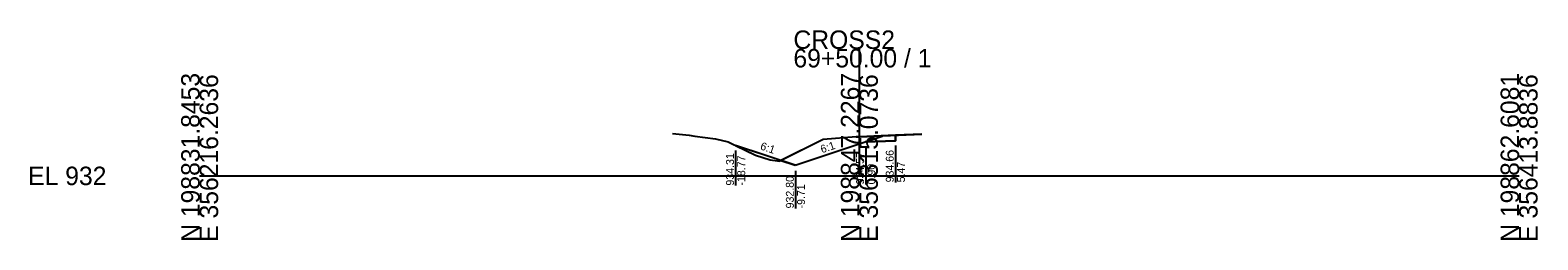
# Model space of a CAD drawing. Extents: x -26 to 203, y -10 to 14021.
# Drawn here: x -25.7 to 202.8, y 10490.3 to 10522.1 of the extents above; entities that cross this region are included whole.
import ezdxf

# ---------------------------------------------------------------- set-up
doc = ezdxf.new("R2010")
doc.units = 0
for name, color, linetype in [('Default', 7, 'Continuous'), ('P_E_XS_Ground', 7, 'Continuous'), ('P_XS', 7, 'Continuous'), ('P_XS_EAR_CommonGrnd', 7, 'Continuous'), ('P_XS_Lane', 7, 'Continuous'), ('P_XS_Rock', 7, 'Continuous')]:
    doc.layers.add(name, color=color, linetype=linetype)

msp = doc.modelspace()

# ---------------------------------------------------------------- linework, layer by layer
at = {"layer": 'Default'}
for p, q in [((100, 10500), (100, 10519.24)), ((0, 10500), (100, 10500)), ((100, 10500), (200, 10500))]:
    msp.add_line(p, q, dxfattribs=at)
at = {"layer": 'P_E_XS_Ground'}
for p, q in [((71.66, 10506.41), (74.2, 10506.18)), ((74.2, 10506.18), (75.08, 10506)), ((75.08, 10506), (78.17, 10505.61)), ((99.5, 10505.92), (94.5, 10505.52)), ((99.5, 10505.92), (100, 10505.94)), ((100, 10505.94), (109.47, 10506.32)), ((109.47, 10506.32), (109.49, 10506.32)), ((78.17, 10505.61), (80.11, 10505.17)), ((80.11, 10505.17), (84.27, 10503.12)), ((94.5, 10505.52), (87.92, 10502.23)), ((84.27, 10503.12), (86.48, 10502.43)), ((86.48, 10502.43), (87.92, 10502.23))]:
    msp.add_line(p, q, dxfattribs=at)
at = {"layer": 'P_XS'}
for p, q in [((100.9, 10505.14), (103.47, 10506)), ((105.47, 10506.16), (103.47, 10506)), ((109.47, 10506.32), (105.47, 10506.16))]:
    msp.add_line(p, q, dxfattribs=at)
at = {"layer": 'P_XS_EAR_CommonGrnd'}
for points in [[(90.29, 10501.6), (100.9, 10505.14), (105.47, 10505.32), (105.47, 10506.16), (100, 10505.94), (99.5, 10505.92), (94.5, 10505.52), (88.11, 10502.32)], [(81.23, 10504.62), (84.27, 10503.12), (86.48, 10502.43), (87.92, 10502.23), (88.11, 10502.32)]]:
    msp.add_lwpolyline(points, close=True, dxfattribs=at)
at = {"layer": 'P_XS_Lane'}
for p, q in [((105.47, 10506.16), (105.47, 10505.32)), ((90.29, 10501.6), (81.23, 10504.62)), ((90.29, 10501.6), (100.9, 10505.14)), ((105.47, 10505.32), (100.9, 10505.14))]:
    msp.add_line(p, q, dxfattribs=at)
at = {"layer": 'P_XS_Rock'}
for p, q in [((81.24, 10503.83), (81.24, 10498.53)), ((100.96, 10504.3), (100.96, 10498.71)), ((105.45, 10504.61), (105.45, 10499.02)), ((90.31, 10500.77), (90.31, 10495.07))]:
    msp.add_line(p, q, dxfattribs=at)

# ---------------------------------------------------------------- texts
at = {"layer": 'Default'}
for s, p in [('CROSS2', (90, 10519.24)), ('69+50.00 / 1', (90, 10516.44)), ('EL 932', (-26, 10498.6))]:
    msp.add_text(s, height=2.8, dxfattribs=at).set_placement(p)
for s, p in [('N 198831.8453', (0, 10490)), ('E 356216.2636', (2.8, 10490)), ('N 198847.2267', (100, 10490)), ('E 356315.0736', (102.8, 10490)), ('N 198862.6081', (200, 10490)), ('E 356413.8836', (202.8, 10490))]:
    msp.add_text(s, height=2.8, rotation=90, dxfattribs=at).set_placement(p)
at = {"layer": 'P_XS_Rock'}
for s, rotation, p in [('934.31', 90, (80.99, 10498.53)), ('6:1', 341.5651, (84.88, 10504.03)), ('6:1', 18.4349, (94.33, 10503.42)), ('934.57', 90, (100.71, 10498.71)), ('934.66', 90, (105.2, 10499.02)), ('-18.77', 90, (82.69, 10498.53)), ('0.90', 90, (102.41, 10498.71)), ('5.47', 90, (106.9, 10499.02)), ('932.80', 90, (90.06, 10495.07)), ('-9.71', 90, (91.76, 10495.07))]:
    msp.add_text(s, height=1.2, rotation=rotation, dxfattribs=at).set_placement(p)

doc.saveas('drawing.dxf')
